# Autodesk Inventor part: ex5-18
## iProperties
Shininess: 64.0
Length Units: 11272
Angle Units: 11279
Time Units: 11290
Mass Units: 11286
Length Display Precision: 3
Angle Display Precision: 2
Compacted: True
Part Number: ex5-18
Document SubType Name: Modeling
Created: 2002-11
Designer: Elise Moss
Density: 0.0
Volumn: 0.0
Area: 0.0
PropertySet Name: Model Information
Control State: 0
Master: False
Checked Out: False
Author: Elise Moss
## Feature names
1. keyhole [Extrusion]
2. Derived Body1 [Tagging]
